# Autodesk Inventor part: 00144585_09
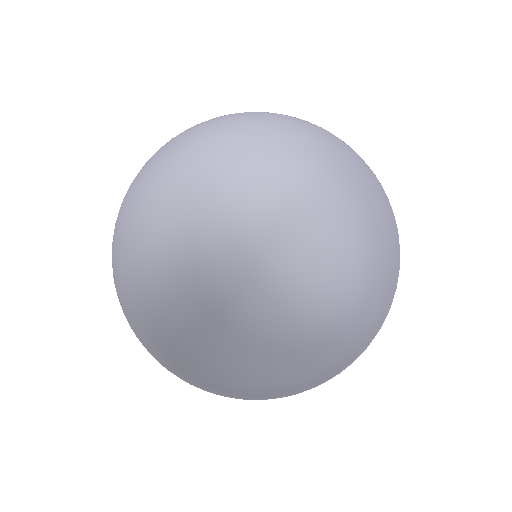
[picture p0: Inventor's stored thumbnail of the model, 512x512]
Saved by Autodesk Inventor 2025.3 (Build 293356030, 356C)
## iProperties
Created: 2021-02
Part Number: 00144585_09
Material: Generico
Document SubType Name: Modeling
Designer: R5800u
Density: 1 g/cm^3
Appearance: Default
Author: TraceParts
Sending System: SolidWorks 2021
Last Author: Albert
Last Saved: 2021-07-28
IsFastener: 1
TYPE: CATASM
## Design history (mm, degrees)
feature "Imported1"
node "Solido1"
